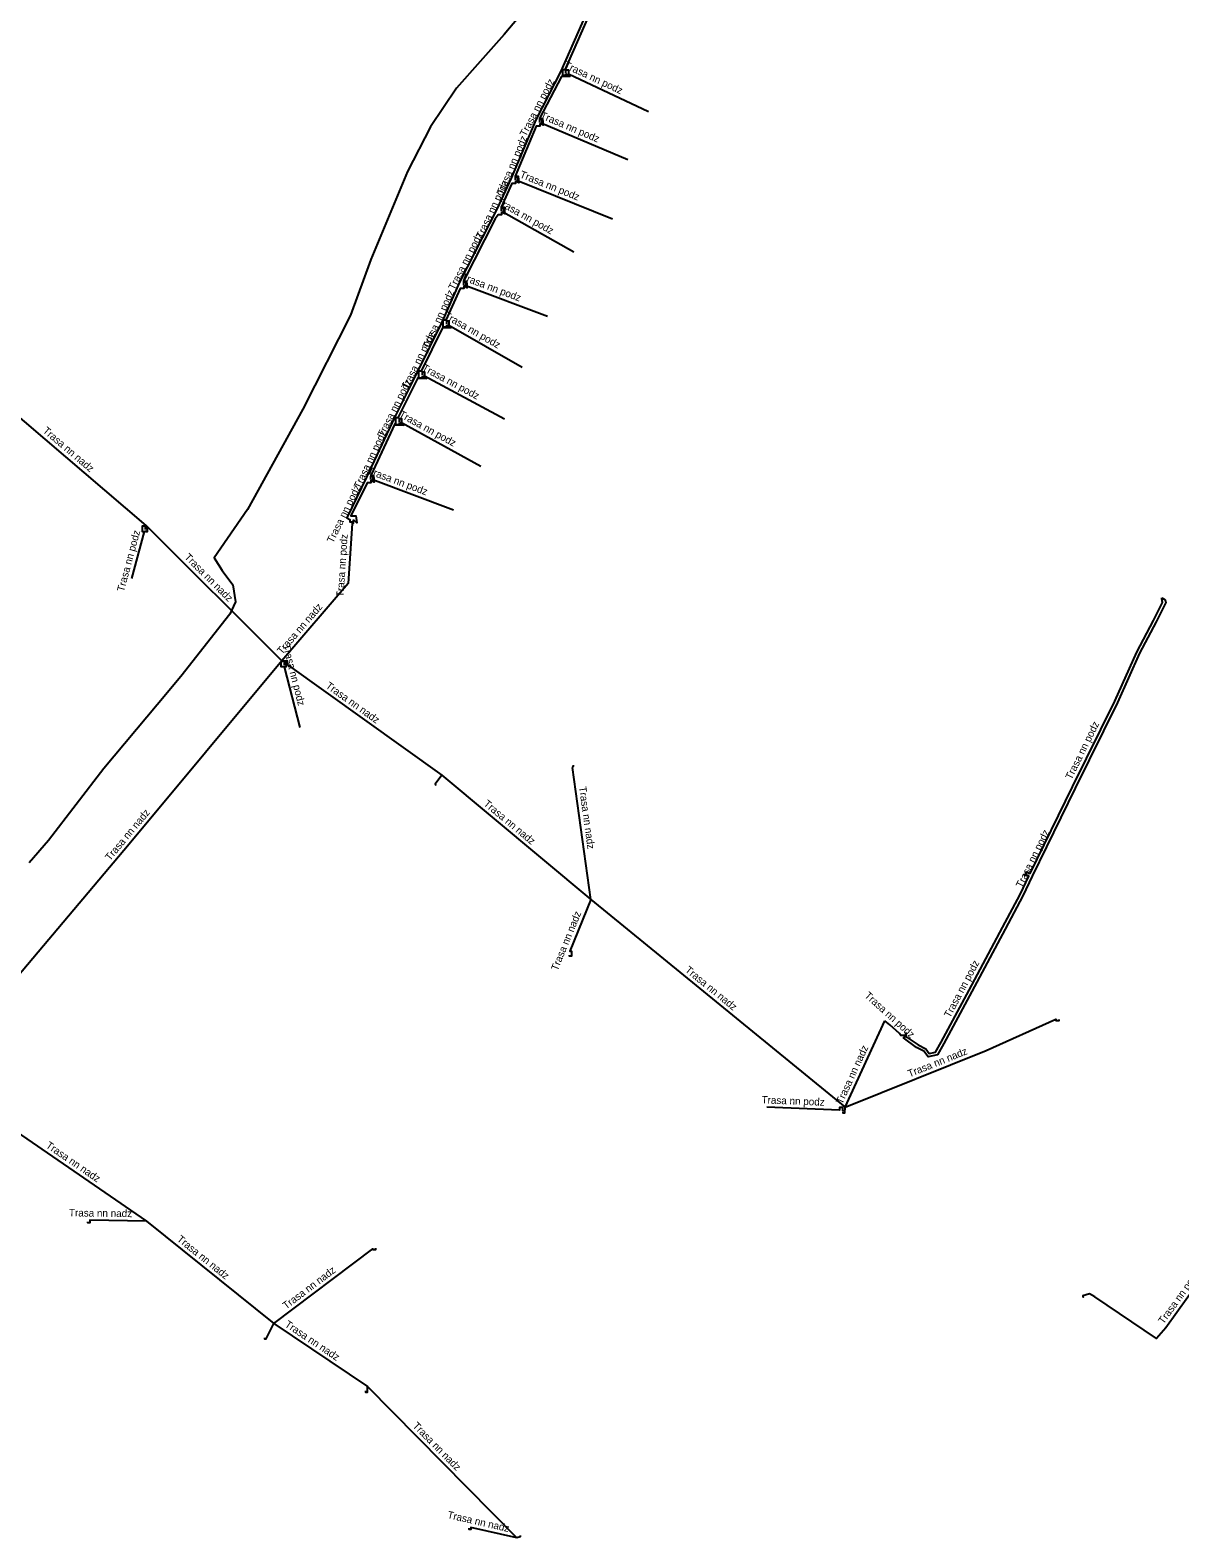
# Model space of a CAD drawing. Extents: x -742082 to -717476, y -1040737 to -1024597.
# Drawn here: x -735845.4 to -735689.8, y -1032557.5 to -1032353.4 of the extents above; entities that cross this region are included whole.
import ezdxf

# ---------------------------------------------------------------- set-up
doc = ezdxf.new("R2010")
doc.units = 0
for name, color, linetype in [('Level 13', 7, 'Continuous'), ('Level 14', 7, 'Continuous'), ('Level 15', 7, 'Continuous'), ('Level 20', 7, 'Continuous'), ('Level 25', 7, 'Continuous')]:
    doc.layers.add(name, color=color, linetype=linetype)

msp = doc.modelspace()

# ---------------------------------------------------------------- linework, layer by layer
at = {"layer": 'Level 13'}
for p, q in [((-735829.69, -1032420.46), (-735848.99, -1032403.96)), ((-735811.36, -1032438.75), (-735829.69, -1032420.46)), ((-735802.37, -1032428.3), (-735811.36, -1032438.75)), ((-735789.7, -1032454.26), (-735769.51, -1032471.07)), ((-735769.51, -1032471.07), (-735735.09, -1032499.21)), ((-735847.3, -1032502.5), (-735829.67, -1032514.61)), ((-735829.67, -1032514.61), (-735812.43, -1032528.49)), ((-735812.43, -1032528.49), (-735799.77, -1032536.99)), ((-735799.77, -1032536.99), (-735779.54, -1032557.5))]:
    msp.add_line(p, q, dxfattribs=at)
for points in [[(-735829.8, -1032421.1), (-735829.8, -1032421.26), (-735829.55, -1032421.26), (-735829.55, -1032420.76), (-735829.69, -1032420.46)], [(-735811.36, -1032438.75), (-735832.02, -1032463.59), (-735849.17, -1032483.94)], [(-735811, -1032439.4), (-735811, -1032439.57), (-735811.45, -1032439.57), (-735811.45, -1032439.06), (-735811.36, -1032438.75)], [(-735811.36, -1032438.75), (-735810.62, -1032438.75), (-735810.62, -1032439.28), (-735789.7, -1032454.26)], [(-735771.9, -1032452.9), (-735771.9, -1032453.06), (-735772, -1032453.2)], [(-735789.7, -1032454.26), (-735790.61, -1032455.45), (-735790.51, -1032455.65)], [(-735735.4, -1032499.8), (-735735.4, -1032499.96), (-735735.14, -1032499.96), (-735735.09, -1032499.21)], [(-735813.7, -1032530.4), (-735813.7, -1032530.56), (-735813.45, -1032530.56), (-735812.43, -1032528.49)], [(-735800, -1032537.6), (-735800, -1032537.76), (-735799.74, -1032537.76), (-735799.74, -1032537.25), (-735799.77, -1032536.99)], [(-735779.1, -1032557.2), (-735779.1, -1032557.36), (-735779.54, -1032557.5)]]:
    msp.add_lwpolyline(points, dxfattribs=at)
at = {"layer": 'Level 14'}
for p, q in [((-735769.51, -1032471.07), (-735772, -1032453.2)), ((-735735.09, -1032499.21), (-735729.72, -1032487.5))]:
    msp.add_line(p, q, dxfattribs=at)
for points in [[(-735769.51, -1032471.07), (-735772.36, -1032478.05), (-735772.15, -1032478.05), (-735772.15, -1032478.76), (-735772.4, -1032478.76), (-735772.4, -1032478.6)], [(-735735.09, -1032499.21), (-735716.01, -1032491.54), (-735706.55, -1032487.26), (-735706.55, -1032487.46), (-735706.1, -1032487.46), (-735706.1, -1032487.3)], [(-735829.67, -1032514.61), (-735837.34, -1032514.51), (-735837.34, -1032514.86), (-735837.6, -1032514.86), (-735837.6, -1032514.7)], [(-735812.43, -1032528.49), (-735799.05, -1032518.36), (-735799.05, -1032518.46), (-735798.6, -1032518.46), (-735798.6, -1032518.3)], [(-735779.54, -1032557.5), (-735785.74, -1032556.08), (-735785.74, -1032556.36), (-735786, -1032556.36), (-735786, -1032556.2)]]:
    msp.add_lwpolyline(points, dxfattribs=at)
at = {"layer": 'Level 15'}
for points in [[(-735734.45, -1032256.73), (-735734.44, -1032257.24), (-735734.89, -1032257.24), (-735731.16, -1032270.07), (-735740.45, -1032291.96), (-735751.54, -1032314.28), (-735759.95, -1032327.84), (-735760.48, -1032329.18), (-735773.58, -1032358.91), (-735776.98, -1032365.52), (-735780.28, -1032373.42), (-735782.18, -1032377.51), (-735787.28, -1032387.51), (-735789.68, -1032392.92), (-735792.98, -1032399.61), (-735796.08, -1032405.81), (-735799.88, -1032413.91), (-735802.56, -1032419.38), (-735802.15, -1032419.62), (-735802.15, -1032419.96), (-735801.64, -1032419.96), (-735801.64, -1032419.69)], [(-735759.64, -1032329.95), (-735760.23, -1032329.61), (-735773.05, -1032358.75), (-735773.35, -1032358.75), (-735773.35, -1032359.46), (-735772.9, -1032359.46), (-735772.9, -1032359.3)], [(-735772.9, -1032359.3), (-735772.35, -1032359.66), (-735773.51, -1032359.66), (-735776.45, -1032365.35), (-735776.05, -1032365.35), (-735775.95, -1032366.26), (-735776.4, -1032366)], [(-735772.9, -1032359.19), (-735772.9, -1032358.75), (-735772.55, -1032358.75), (-735772.55, -1032359.31), (-735761.7, -1032364.4)], [(-735776.4, -1032365.89), (-735776.4, -1032365.45), (-735776.15, -1032365.45), (-735776.15, -1032365.95), (-735764.5, -1032370.9)], [(-735776.4, -1032366), (-735776.4, -1032366.36), (-735776.9, -1032366.36), (-735779.74, -1032373.15), (-735779.34, -1032373.15), (-735779.25, -1032374.06), (-735779.7, -1032373.8)], [(-735779.7, -1032373.8), (-735779.7, -1032374.16), (-735780.19, -1032374.16), (-735781.66, -1032377.35), (-735781.24, -1032377.35), (-735781.15, -1032378.26), (-735781.6, -1032378)], [(-735779.7, -1032373.69), (-735779.7, -1032373.25), (-735779.45, -1032373.25), (-735779.45, -1032373.74), (-735766.6, -1032378.9)], [(-735781.6, -1032378), (-735781.6, -1032378.36), (-735782.07, -1032378.36), (-735782.45, -1032378.93), (-735786.75, -1032387.35), (-735786.34, -1032387.35), (-735786.25, -1032388.26), (-735786.7, -1032388)], [(-735781.6, -1032377.89), (-735781.6, -1032377.45), (-735781.34, -1032377.45), (-735781.34, -1032378), (-735771.8, -1032383.4)], [(-735786.7, -1032388), (-735786.7, -1032388.36), (-735787.22, -1032388.36), (-735789.13, -1032392.65), (-735789.55, -1032392.65), (-735789.55, -1032393.56), (-735789, -1032393.56), (-735789, -1032393.3)], [(-735786.7, -1032387.89), (-735786.7, -1032387.45), (-735786.45, -1032387.45), (-735786.45, -1032387.93), (-735775.4, -1032392.1)], [(-735789, -1032393.3), (-735788.45, -1032393.66), (-735789.6, -1032393.66), (-735792.5, -1032399.55), (-735792.85, -1032399.55), (-735792.85, -1032400.46), (-735792.3, -1032400.46), (-735792.3, -1032400.2)], [(-735789, -1032393.19), (-735789, -1032392.75), (-735788.74, -1032392.75), (-735788.74, -1032393.3), (-735778.8, -1032399)], [(-735792.3, -1032400.2), (-735791.75, -1032400.56), (-735792.95, -1032400.56), (-735792.95, -1032400.45), (-735795.65, -1032405.85), (-735795.95, -1032405.85), (-735795.95, -1032406.76), (-735795.4, -1032406.76), (-735795.4, -1032406.5)], [(-735792.3, -1032400.09), (-735792.3, -1032399.65), (-735792.05, -1032399.65), (-735792.05, -1032400.19), (-735781.2, -1032406)], [(-735795.4, -1032406.5), (-735794.85, -1032406.86), (-735796.05, -1032406.86), (-735796.05, -1032406.69), (-735799.32, -1032413.65), (-735798.95, -1032413.65), (-735798.85, -1032414.56), (-735799.3, -1032414.3)], [(-735795.4, -1032406.39), (-735795.4, -1032405.95), (-735795.15, -1032405.95), (-735795.15, -1032406.49), (-735784.4, -1032412.4)], [(-735799.3, -1032414.3), (-735799.3, -1032414.66), (-735799.8, -1032414.66), (-735802, -1032419.15), (-735801.34, -1032419.15), (-735801.19, -1032420.06), (-735801.64, -1032419.69)], [(-735799.3, -1032414.19), (-735799.3, -1032413.75), (-735799.05, -1032413.75), (-735799.05, -1032414.23), (-735788.1, -1032418.3)], [(-735829.8, -1032420.99), (-735829.8, -1032420.55), (-735830.25, -1032420.55), (-735830.25, -1032421.26), (-735830, -1032421.26), (-735831.7, -1032427.6)], [(-735801.69, -1032419.69), (-735801.69, -1032420.16), (-735801.84, -1032420.16), (-735802.37, -1032428.3)], [(-735692.24, -1032430.23), (-735691.79, -1032430.49), (-735691.68, -1032430.86), (-735693.01, -1032433.49), (-735695.24, -1032437.74), (-735698.23, -1032444.41), (-735703.96, -1032455.99), (-735709.78, -1032467.92), (-735711.05, -1032470.57), (-735713.44, -1032475.07), (-735717.93, -1032483.52), (-735721.72, -1032490.58), (-735722.59, -1032492.09), (-735723.86, -1032492.36), (-735724.45, -1032491.59), (-735725.42, -1032491.1), (-735727.2, -1032489.8), (-735726.89, -1032489.57), (-735726.89, -1032489.1)], [(-735710.82, -1032467.58), (-735710.57, -1032467.74), (-735710.57, -1032467.33), (-735710.05, -1032467.57), (-735704.32, -1032455.82), (-735698.6, -1032444.24), (-735695.6, -1032437.57), (-735693.36, -1032433.31), (-735692.13, -1032430.86), (-735692.24, -1032430.39), (-735692.24, -1032430.23)], [(-735811, -1032439.29), (-735811, -1032438.85), (-735810.74, -1032438.85), (-735810.74, -1032439.57), (-735811.01, -1032439.57), (-735808.9, -1032447.8)], [(-735726.87, -1032489.1), (-735726.87, -1032489.67), (-735726.82, -1032489.67), (-735725.21, -1032490.75), (-735724.19, -1032491.28), (-735723.7, -1032491.92), (-735722.85, -1032491.73), (-735722.08, -1032490.39), (-735718.28, -1032483.33), (-735713.8, -1032474.88), (-735711.41, -1032470.39), (-735710.22, -1032467.93), (-735710.47, -1032467.82), (-735710.47, -1032467.84), (-735710.82, -1032467.84), (-735710.82, -1032467.58)], [(-735726.92, -1032489.1), (-735726.92, -1032489.47), (-735727.57, -1032489.47), (-735727.74, -1032489.22), (-735729.03, -1032488.06), (-735729.72, -1032487.5)], [(-735735.4, -1032499.69), (-735735.4, -1032499.25), (-735735.85, -1032499.25), (-735735.85, -1032499.59), (-735745.7, -1032499.2)], [(-735673.16, -1032526.17), (-735673.22, -1032526.27), (-735673.52, -1032526.02), (-735674.27, -1032528.61), (-735674.5, -1032528.82), (-735677.13, -1032530.29), (-735683.05, -1032526.13), (-735685.66, -1032523.15), (-735687.2, -1032522.85), (-735691.69, -1032529.07), (-735692.95, -1032530.51), (-735701.29, -1032524.87), (-735702.03, -1032524.47), (-735702.92, -1032524.74), (-735702.88, -1032524.92), (-735702.83, -1032524.83)]]:
    msp.add_lwpolyline(points, dxfattribs=at)
at = {"layer": 'Level 25'}
msp.add_lwpolyline([(-735775.44, -1032347.01), (-735781.24, -1032353.96), (-735784.52, -1032357.62), (-735787.68, -1032361.22), (-735791.22, -1032366.47), (-735794.32, -1032372.53), (-735799.28, -1032384.44), (-735802.07, -1032391.96), (-735808.51, -1032404.69), (-735815.99, -1032418.28), (-735820.52, -1032424.8), (-735819.44, -1032426.52), (-735817.98, -1032428.49), (-735817.6, -1032430.77), (-735818.37, -1032432.44), (-735825.01, -1032440.88), (-735828.21, -1032444.74), (-735835.42, -1032453.36), (-735842.95, -1032463.08), (-735845.53, -1032466.1)], dxfattribs=at)

# ---------------------------------------------------------------- texts
at = {"layer": 'Level 20'}
for s, rotation, p in [('Trasa nn podz', 334.8721, (-735773.22, -1032358.45)), ('Trasa nn podz', 62.7445, (-735778.31, -1032367.87)), ('Trasa nn podz', 336.9746, (-735776.46, -1032365.27)), ('Trasa nn podz', 67.3286, (-735781.39, -1032375.81)), ('Trasa nn podz', 65.1364, (-735784.23, -1032381.71)), ('Trasa nn podz', 338.1237, (-735779.22, -1032373.29)), ('Trasa nn podz', 330.505, (-735782.34, -1032376.86)), ('Trasa nn podz', 62.9785, (-735787.98, -1032388.66)), ('Trasa nn podz', 339.3339, (-735787.18, -1032387.12)), ('Trasa nn podz', 66.0381, (-735791.44, -1032396.62)), ('Trasa nn podz', 330.1953, (-735789.52, -1032392.28)), ('Trasa nn podz', 63.7778, (-735794.33, -1032402.14)), ('Trasa nn podz', 331.8214, (-735792.47, -1032399.39)), ('Trasa nn podz', 63.4352, (-735797.57, -1032408.57)), ('Trasa nn podz', 331.2091, (-735795.59, -1032405.68)), ('Trasa nn nadz', 319.4721, (-735843.79, -1032407.74)), ('Trasa nn podz', 64.8672, (-735800.76, -1032415.55)), ('Trasa nn podz', 339.6109, (-735799.84, -1032413.4)), ('Trasa nn podz', 63.8691, (-735804.41, -1032422.91)), ('Trasa nn podz', 74.9621, (-735832.72, -1032429.48)), ('Trasa nn podz', 86.2515, (-735802.99, -1032430.16)), ('Trasa nn nadz', 315.0626, (-735824.62, -1032424.81)), ('Trasa nn nadz', 49.295, (-735811.34, -1032437.97)), ('Trasa nn podz', 284.3493, (-735811.24, -1032436.65)), ('Trasa nn nadz', 324.4019, (-735805.5, -1032442.34)), ('Trasa nn podz', 63.6929, (-735704.44, -1032454.93)), ('Trasa nn nadz', 320.2196, (-735784.12, -1032458.26)), ('Trasa nn nadz', 277.9325, (-735771.13, -1032455.84)), ('Trasa nn nadz', 50.2489, (-735834.6, -1032465.91)), ('Trasa nn podz', 64.0123, (-735711.14, -1032469.59)), ('Trasa nn nadz', 67.8087, (-735774.02, -1032480.81)), ('Trasa nn nadz', 320.7324, (-735756.85, -1032480.77)), ('Trasa nn podz', 62.0366, (-735720.89, -1032487.17)), ('Trasa nn podz', 317.9111, (-735732.55, -1032484.2)), ('Trasa nn nadz', 65.3668, (-735735.48, -1032498.86)), ('Trasa nn nadz', 21.8997, (-735726.38, -1032495.17)), ('Trasa nn podz', 357.7544, (-735746.42, -1032498.67)), ('Trasa nn nadz', 325.5149, (-735843.38, -1032504.58)), ('Trasa nn nadz', 359.2153, (-735840.17, -1032513.97)), ('Trasa nn nadz', 321.1623, (-735825.63, -1032517.22)), ('Trasa nn nadz', 37.1161, (-735810.77, -1032526.61)), ('Trasa nn podz', 54.1758, (-735691.99, -1032528.64)), ('Trasa nn nadz', 326.1224, (-735811.04, -1032528.82)), ('Trasa nn nadz', 314.6062, (-735793.71, -1032542.42)), ('Trasa nn nadz', 347.1204, (-735789, -1032554.82))]:
    msp.add_text(s, height=1, rotation=rotation, dxfattribs=at).set_placement(p)

doc.saveas('drawing.dxf')
